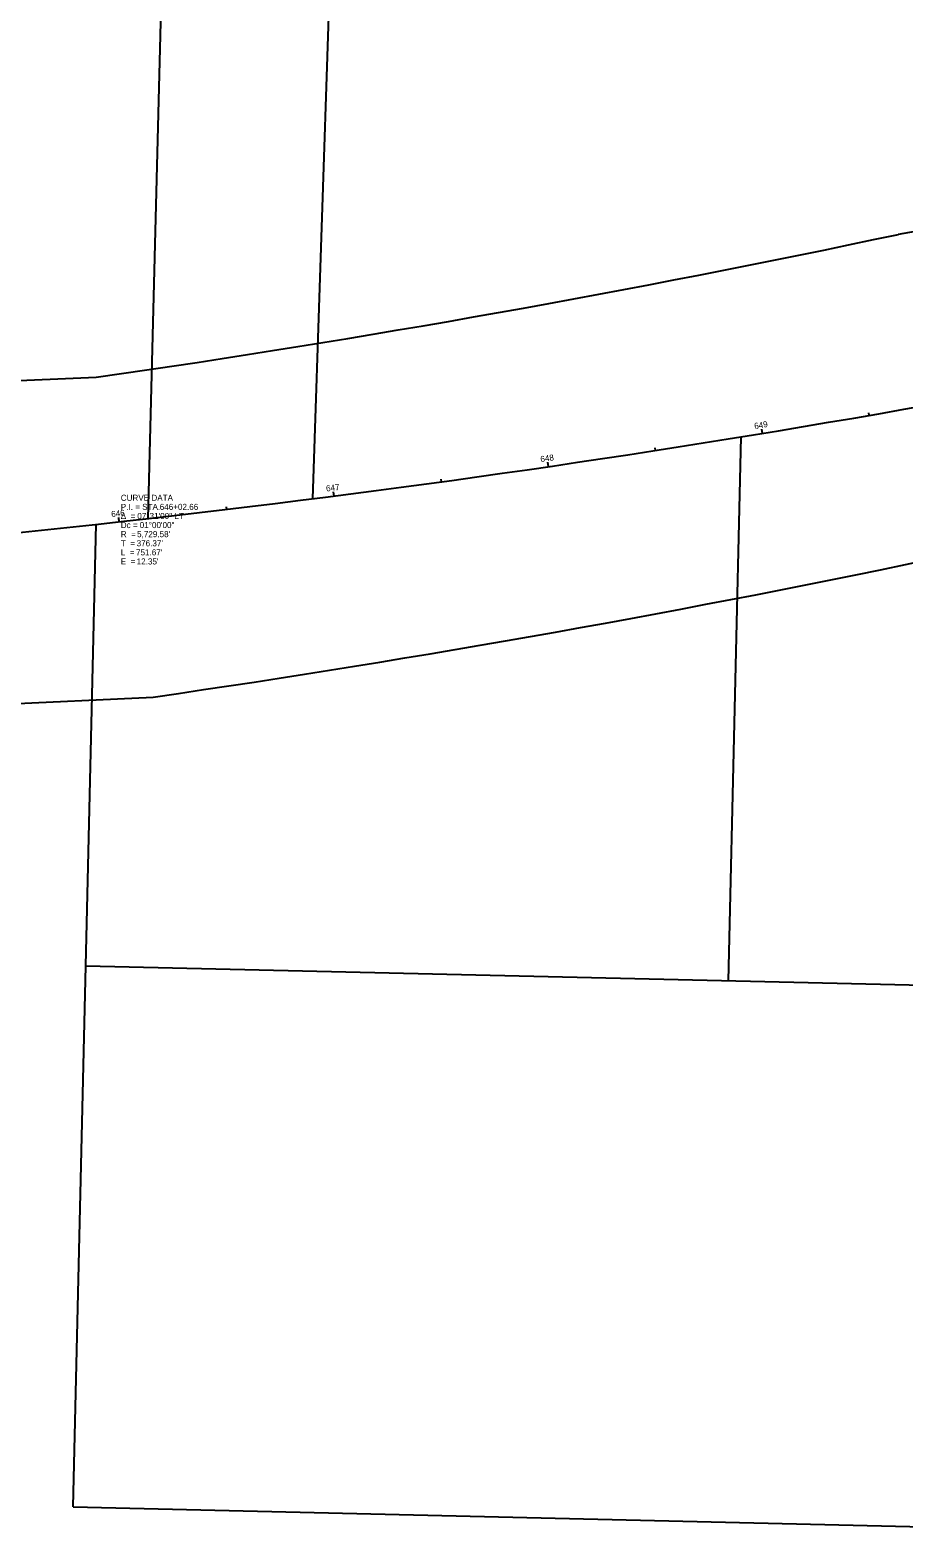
# Model space of a CAD drawing. Extents: x 1390087 to 1393932, y 303908 to 305061.
# Drawn here: x 1391688 to 1392092, y 303908 to 304605 of the extents above; entities that cross this region are included whole.
import ezdxf

# ---------------------------------------------------------------- set-up
doc = ezdxf.new("R2010")
doc.units = 0
for name, color, linetype in [('DV_X_Property_Line', 7, 'Continuous'), ('RW_X_CL', 7, 'Continuous'), ('RW_X_CL_100_Curve_Data', 7, 'Continuous'), ('RW_X_CL_100_Stations', 7, 'Continuous'), ('RW_X_Esmt_SH', 7, 'Continuous')]:
    doc.layers.add(name, color=color, linetype=linetype)

msp = doc.modelspace()

# ---------------------------------------------------------------- linework, layer by layer
at = {"layer": 'DV_X_Property_Line'}
for p, q in [((1391756.75, 304937.07), (1391742.54, 304379.08)), ((1391828.58, 304689.27), (1391818.54, 304388.2)), ((1392010.66, 304165.6), (1392016.54, 304416.82)), ((1391713.86, 304172.54), (1391718.63, 304376.42)), ((1391708.02, 303922.61), (1391713.86, 304172.54)), ((1391713.86, 304172.54), (1392326.68, 304158.21)), ((1391708.02, 303922.61), (1392320.18, 303908.29))]:
    msp.add_line(p, q, dxfattribs=at)
at = {"layer": 'RW_X_CL'}
msp.add_arc((1391097.92, 310072.28), 5729.58, 272.589038, 280.105736, dxfattribs=at)
msp.add_arc((1391097.92, 310072.28), 5729.58, 272.589038, 280.105736, dxfattribs=at)
at = {"layer": 'RW_X_CL_100_Stations'}
for p, q in [((1392075.72, 304426.75), (1392075.52, 304427.93)), ((1392026.42, 304418.43), (1392026.09, 304420.41)), ((1391977.05, 304410.55), (1391976.86, 304411.73)), ((1391927.6, 304403.09), (1391927.31, 304405.07)), ((1391878.1, 304396.07), (1391877.94, 304397.26)), ((1391828.54, 304389.47), (1391828.28, 304391.46)), ((1391729.25, 304377.59), (1391729.03, 304379.58)), ((1391778.92, 304383.31), (1391778.78, 304384.51))]:
    msp.add_line(p, q, dxfattribs=at)
at = {"layer": 'RW_X_Esmt_SH'}
for p, q in [((1392089.23, 304510.35), (1392165.07, 304523.87)), ((1391353.12, 304428.47), (1391718.69, 304444.31)), ((1391359.89, 304278.62), (1391745.01, 304296.64))]:
    msp.add_line(p, q, dxfattribs=at)
for centre, radius, start, end in [((1390913.2, 310036.17), 5649.58, 278.19682, 282.01462), ((1390911.43, 310046.1), 5809.58, 278.249443, 281.961997)]:
    msp.add_arc(centre, radius, start, end, dxfattribs=at)

# ---------------------------------------------------------------- texts
at = {"layer": 'RW_X_CL_100_Curve_Data'}
for s, p in [('CURVE DATA', (1391730, 304387.27)), ('Δ  = ', (1391730, 304378.87)), ('P.I. = STA. ', (1391730, 304383.07)), ('07°31\'00" LT', (1391737.64, 304378.87)), ('646+02.66', (1391747.99, 304383.07)), ('Dc = ', (1391730, 304374.67)), ('R  = ', (1391730, 304370.47)), ("5,729.58'", (1391737.53, 304370.47)), ('01°00\'00"', (1391738.74, 304374.67)), ('T  = ', (1391730, 304366.27)), ("376.37'", (1391737.32, 304366.27)), ('L  = ', (1391730, 304362.07)), ('E  = ', (1391730, 304357.87)), ("751.67'", (1391737.03, 304362.07)), ("12.35'", (1391737.34, 304357.87))]:
    msp.add_text(s, height=2.8, dxfattribs=at).set_placement(p)
at = {"layer": 'RW_X_CL_100_Stations'}
for s, rotation, p in [('649', 9.32614, (1392022.83, 304420.38)), ('648', 8.32614, (1391924.03, 304405.09)), ('647', 7.32614, (1391825, 304391.54)), ('646', 6.32614, (1391725.74, 304379.71))]:
    msp.add_text(s, height=2.8, rotation=rotation, dxfattribs=at).set_placement(p)

doc.saveas('drawing.dxf')
